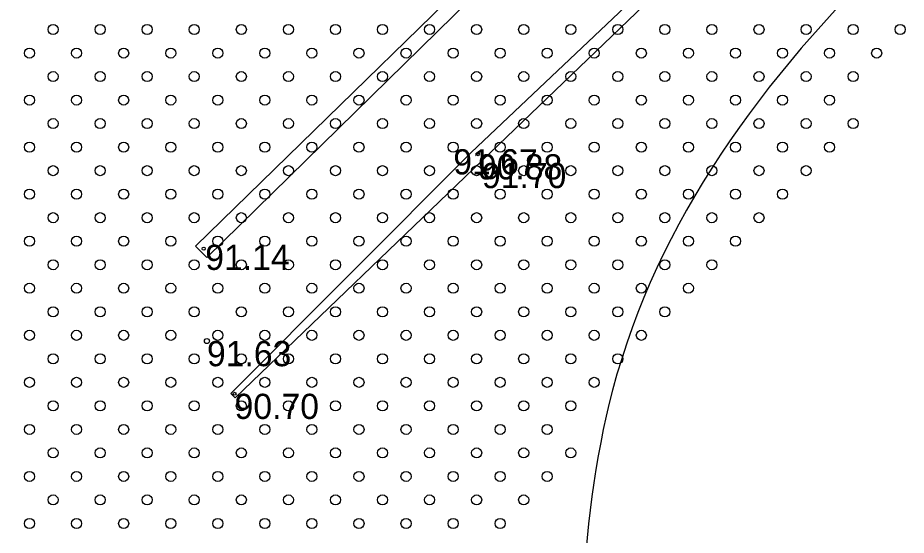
# Model space of a CAD drawing. Extents: x 316000 to 728450, y 314368 to 726000.
# Drawn here: x 725971.8 to 726103.9, y 315036.8 to 315113.8 of the extents above; entities that cross this region are included whole.
import ezdxf

# ---------------------------------------------------------------- set-up
doc = ezdxf.new("R2010")
doc.units = 0
for name, color, linetype in [('HIDG_ELEM_####_####_#', 7, 'Continuous'), ('HIDG_GRAV_####_####_#', 7, 'Continuous'), ('RELJ_AATZ_####_TKST_#', 7, 'Continuous'), ('RELJ_ELEM_####_####_#', 7, 'Continuous'), ('RELJ_HORZ_PAMT_####_#', 7, 'Continuous'), ('RELJ_NOGA_####_####_#', 7, 'Continuous'), ('TERT_ELEM_####_####_#', 7, 'Continuous'), ('TERT_KONT_####_####_#', 7, 'Continuous')]:
    doc.layers.add(name, color=color, linetype=linetype)

msp = doc.modelspace()

# ---------------------------------------------------------------- linework, layer by layer
at = {"layer": 'HIDG_ELEM_####_####_#'}
for centre in [(726040.19, 315093.44), (725999.4, 315079.39), (726004, 315057.8)]:
    msp.add_circle(centre, 0.225, dxfattribs=at)
at = {"layer": 'HIDG_GRAV_####_####_#'}
for points in [[(726040.8, 315092.53), (726091.49, 315141.17), (726090.49, 315142.31), (726039.19, 315093.71)], [(726054.94, 315135.17), (726056.2, 315133.35), (725999.87, 315078.06), (725998.18, 315079.78), (726054.94, 315135.17)], [(726039.19, 315093.71), (726003.45, 315057.83), (726004.1, 315057.18), (726040.8, 315092.53)]]:
    msp.add_lwpolyline(points, dxfattribs=at)
at = {"layer": 'RELJ_ELEM_####_####_#'}
msp.add_circle((725999.89, 315065.65), 0.375, dxfattribs=at)
at = {"layer": 'RELJ_HORZ_PAMT_####_#'}
msp.add_spline([(726081.57, 315247.05), (726057.5, 315241.5), (726036.5, 315213.5), (725977, 315161), (725966.5, 315108.5), (725903.5, 315045.5), (725862.12, 315076.6), (725805.5, 315130), (725759.7, 315178.88), (725709.89, 315228.8), (725646.99, 315287.19), (725634.68, 315314.96), (725629.04, 315327.48), (725557.35, 315340.26), (725478.3, 315344.16)], degree=3, dxfattribs=at)
at = {"layer": 'RELJ_NOGA_####_####_#'}
for points in [[(726259.12, 315084.51), (726262.72, 315089.26), (726261.56, 315090.84), (726260.2, 315092.42), (726257.29, 315095.53), (726218.91, 315136.38), (726180.31, 315176.84), (726128.67, 315229.97), (726063.7, 315298.11), (725999.9, 315366.09), (725937.21, 315432.09), (725876.35, 315495.23), (725810.58, 315563.08), (725744.7, 315632.91)], [(725740.86, 315626.98), (725805.54, 315558.12), (725870.39, 315491.15), (725932.8, 315426.8), (725994.98, 315360.84), (726059.66, 315292.12), (726075.75, 315275.46), (726092.08, 315259.04), (726108.47, 315242.67), (726124.69, 315226.14), (726193.27, 315154.03), (726250.06, 315092.6), (726256.32, 315085.83), (726258.82, 315084.29), (726259.12, 315084.51)]]:
    msp.add_spline(points, degree=3, dxfattribs=at)
at = {"layer": 'TERT_ELEM_####_####_#'}
for centre in [(725977, 315112), (725984, 315112), (725991, 315112), (725998, 315112), (726005, 315112), (726012, 315112), (726019, 315112), (726026, 315112), (726033, 315112), (726040, 315112), (726047, 315112), (726054, 315112), (726061, 315112), (726068, 315112), (726075, 315112), (726082, 315112), (726089, 315112), (726096, 315112), (726103, 315112), (725973.5, 315108.5), (725980.5, 315108.5), (725987.5, 315108.5), (725994.5, 315108.5), (726001.5, 315108.5), (726008.5, 315108.5), (726015.5, 315108.5), (726022.5, 315108.5), (726029.5, 315108.5), (726036.5, 315108.5), (726043.5, 315108.5), (726050.5, 315108.5), (726057.5, 315108.5), (726064.5, 315108.5), (726071.5, 315108.5), (726078.5, 315108.5), (726085.5, 315108.5), (726092.5, 315108.5), (726099.5, 315108.5), (725977, 315105), (725984, 315105), (725991, 315105), (725998, 315105), (726005, 315105), (726012, 315105), (726019, 315105), (726026, 315105), (726033, 315105), (726040, 315105), (726047, 315105), (726054, 315105), (726061, 315105), (726068, 315105), (726075, 315105), (726082, 315105), (726089, 315105), (726096, 315105), (725973.5, 315101.5), (725980.5, 315101.5), (725987.5, 315101.5), (725994.5, 315101.5), (726001.5, 315101.5), (726008.5, 315101.5), (726015.5, 315101.5), (726022.5, 315101.5), (726029.5, 315101.5), (726036.5, 315101.5), (726043.5, 315101.5), (726050.5, 315101.5), (726057.5, 315101.5), (726064.5, 315101.5), (726071.5, 315101.5), (726078.5, 315101.5), (726085.5, 315101.5), (726092.5, 315101.5), (725977, 315098), (725984, 315098), (725991, 315098), (725998, 315098), (726005, 315098), (726012, 315098), (726019, 315098), (726026, 315098), (726033, 315098), (726040, 315098), (726047, 315098), (726054, 315098), (726061, 315098), (726068, 315098), (726075, 315098), (726082, 315098), (726089, 315098), (726096, 315098), (725973.5, 315094.5), (725980.5, 315094.5), (725987.5, 315094.5), (725994.5, 315094.5), (726001.5, 315094.5), (726008.5, 315094.5), (726015.5, 315094.5), (726022.5, 315094.5), (726029.5, 315094.5), (726036.5, 315094.5), (726043.5, 315094.5), (726050.5, 315094.5), (726057.5, 315094.5), (726064.5, 315094.5), (726071.5, 315094.5), (726078.5, 315094.5), (726085.5, 315094.5), (726092.5, 315094.5), (725977, 315091), (725984, 315091), (725991, 315091), (725998, 315091), (726005, 315091), (726012, 315091), (726019, 315091), (726026, 315091), (726033, 315091), (726040, 315091), (726047, 315091), (726054, 315091), (726061, 315091), (726068, 315091), (726075, 315091), (726082, 315091), (726089, 315091), (725973.5, 315087.5), (725980.5, 315087.5), (725987.5, 315087.5), (725994.5, 315087.5), (726001.5, 315087.5), (726008.5, 315087.5), (726015.5, 315087.5), (726022.5, 315087.5), (726029.5, 315087.5), (726036.5, 315087.5), (726043.5, 315087.5), (726050.5, 315087.5), (726057.5, 315087.5), (726064.5, 315087.5), (726071.5, 315087.5), (726078.5, 315087.5), (726085.5, 315087.5), (725977, 315084), (725984, 315084), (725991, 315084), (725998, 315084), (726005, 315084), (726012, 315084), (726019, 315084), (726026, 315084), (726033, 315084), (726040, 315084), (726047, 315084), (726054, 315084), (726061, 315084), (726068, 315084), (726075, 315084), (726082, 315084), (725973.5, 315080.5), (725980.5, 315080.5), (725987.5, 315080.5), (725994.5, 315080.5), (726001.5, 315080.5), (726008.5, 315080.5), (726015.5, 315080.5), (726022.5, 315080.5), (726029.5, 315080.5), (726036.5, 315080.5), (726043.5, 315080.5), (726050.5, 315080.5), (726057.5, 315080.5), (726064.5, 315080.5), (726071.5, 315080.5), (726078.5, 315080.5), (725977, 315077), (725984, 315077), (725991, 315077), (725998, 315077), (726005, 315077), (726012, 315077), (726019, 315077), (726026, 315077), (726033, 315077), (726040, 315077), (726047, 315077), (726054, 315077), (726061, 315077), (726068, 315077), (726075, 315077), (725973.5, 315073.5), (725980.5, 315073.5), (725987.5, 315073.5), (725994.5, 315073.5), (726001.5, 315073.5), (726008.5, 315073.5), (726015.5, 315073.5), (726022.5, 315073.5), (726029.5, 315073.5), (726036.5, 315073.5), (726043.5, 315073.5), (726050.5, 315073.5), (726057.5, 315073.5), (726064.5, 315073.5), (726071.5, 315073.5), (725977, 315070), (725984, 315070), (725991, 315070), (725998, 315070), (726005, 315070), (726012, 315070), (726019, 315070), (726026, 315070), (726033, 315070), (726040, 315070), (726047, 315070), (726054, 315070), (726061, 315070), (726068, 315070), (725973.5, 315066.5), (725980.5, 315066.5), (725987.5, 315066.5), (725994.5, 315066.5), (726001.5, 315066.5), (726008.5, 315066.5), (726015.5, 315066.5), (726022.5, 315066.5), (726029.5, 315066.5), (726036.5, 315066.5), (726043.5, 315066.5), (726050.5, 315066.5), (726057.5, 315066.5), (726064.5, 315066.5), (725977, 315063), (725984, 315063), (725991, 315063), (725998, 315063), (726005, 315063), (726012, 315063), (726019, 315063), (726026, 315063), (726033, 315063), (726040, 315063), (726047, 315063), (726054, 315063), (726061, 315063), (725973.5, 315059.5), (725980.5, 315059.5), (725987.5, 315059.5), (725994.5, 315059.5), (726001.5, 315059.5), (726008.5, 315059.5), (726015.5, 315059.5), (726022.5, 315059.5), (726029.5, 315059.5), (726036.5, 315059.5), (726043.5, 315059.5), (726050.5, 315059.5), (726057.5, 315059.5), (725977, 315056), (725984, 315056), (725991, 315056), (725998, 315056), (726005, 315056), (726012, 315056), (726019, 315056), (726026, 315056), (726033, 315056), (726040, 315056), (726047, 315056), (726054, 315056), (725973.5, 315052.5), (725980.5, 315052.5), (725987.5, 315052.5), (725994.5, 315052.5), (726001.5, 315052.5), (726008.5, 315052.5), (726015.5, 315052.5), (726022.5, 315052.5), (726029.5, 315052.5), (726036.5, 315052.5), (726043.5, 315052.5), (726050.5, 315052.5), (725977, 315049), (725984, 315049), (725991, 315049), (725998, 315049), (726005, 315049), (726012, 315049), (726019, 315049), (726026, 315049), (726033, 315049), (726040, 315049), (726047, 315049), (726054, 315049), (725973.5, 315045.5), (725980.5, 315045.5), (725987.5, 315045.5), (725994.5, 315045.5), (726001.5, 315045.5), (726008.5, 315045.5), (726015.5, 315045.5), (726022.5, 315045.5), (726029.5, 315045.5), (726036.5, 315045.5), (726043.5, 315045.5), (726050.5, 315045.5), (725977, 315042), (725984, 315042), (725991, 315042), (725998, 315042), (726005, 315042), (726012, 315042), (726019, 315042), (726026, 315042), (726033, 315042), (726040, 315042), (726047, 315042), (725973.5, 315038.5), (725980.5, 315038.5), (725987.5, 315038.5), (725994.5, 315038.5), (726001.5, 315038.5), (726008.5, 315038.5), (726015.5, 315038.5), (726022.5, 315038.5), (726029.5, 315038.5), (726036.5, 315038.5), (726043.5, 315038.5)]:
    msp.add_circle(centre, 0.75, dxfattribs=at)
at = {"layer": 'TERT_KONT_####_####_#'}
msp.add_spline([(726171.05, 315177.78), (726060.22, 315058.34), (726046.85, 314926.57), (725966, 314840.49), (725918.95, 314808.85), (725841.04, 314808.85), (725695.46, 314898.17)], degree=3, dxfattribs=at)

# ---------------------------------------------------------------- texts
at = {"layer": 'RELJ_AATZ_####_TKST_#'}
for s, p in [('91.67', (726036.53, 315090.44)), ('90.88', (726040.19, 315089.69)), ('91.70', (726040.79, 315088.4)), ('91.14', (725999.64, 315076.23)), ('91.63', (725999.89, 315061.9)), ('90.70', (726004, 315054.05))]:
    msp.add_text(s, height=3.75, dxfattribs=at).set_placement(p)

doc.saveas('drawing.dxf')
